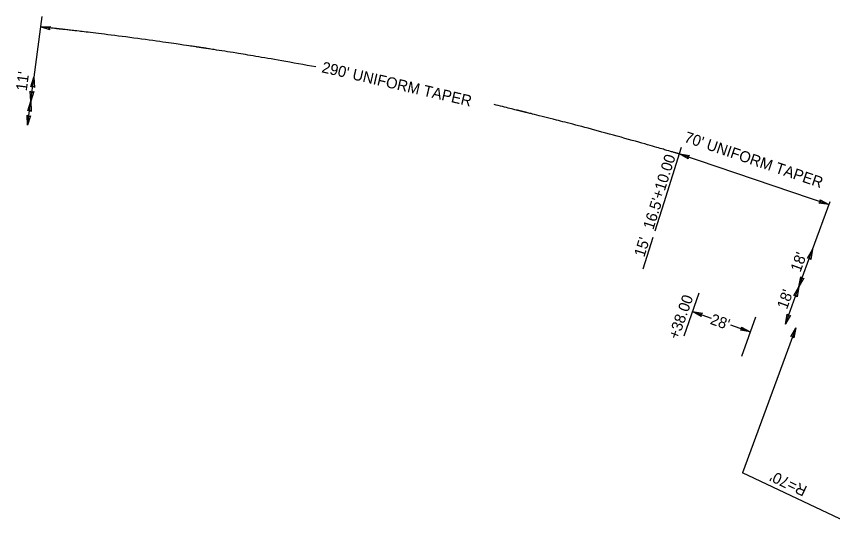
# Model space of a CAD drawing. Extents: x 2320991 to 2332664, y 598057 to 612602.
# Drawn here: x 2328502.8 to 2328873.9, y 607955.8 to 608193.1 of the extents above; entities that cross this region are included whole.
import ezdxf

# ---------------------------------------------------------------- set-up
doc = ezdxf.new("R2010")
doc.units = 0
for name, color, linetype in [('Prop Dimension', 7, 'Continuous'), ('Prop Dimension Text', 7, 'Continuous'), ('Prop Terminator CELL', 7, 'Continuous')]:
    doc.layers.add(name, color=color, linetype=linetype)

msp = doc.modelspace()

# ---------------------------------------------------------------- linework, layer by layer
at = {"layer": 'Prop Dimension'}
for p, q in [((2328514.32, 608193.06), (2328510.73, 608165.39)), ((2328509.32, 608154.49), (2328510.73, 608165.39)), ((2328507.91, 608143.58), (2328509.32, 608154.49)), ((2328797.22, 608108.44), (2328805.16, 608133.59)), ((2328804.19, 608130.53), (2328872.17, 608107.52)), ((2328793.16, 608095.56), (2328797.22, 608108.44)), ((2328864.7, 608087.11), (2328872.67, 608109)), ((2328787.75, 608078.4), (2328792.26, 608092.7)), ((2328858.54, 608070.19), (2328864.7, 608087.11)), ((2328852.37, 608053.28), (2328858.54, 608070.19)), ((2328813.01, 608067.26), (2328806.15, 608047.83)), ((2328810.09, 608058.98), (2328818.6, 608055.98)), ((2328838.81, 608056.43), (2328832.48, 608038.53)), ((2328827.41, 608052.87), (2328836.42, 608049.68)), ((2328857.08, 608051.56), (2328832.86, 607985.72)), ((2328896.13, 607955.8), (2328832.86, 607985.72))]:
    msp.add_line(p, q, dxfattribs=at)
for points in [[(2328586.95, 608178.82), (2328586.94, 608178.82), (2328586.93, 608178.82)], [(2328732.6, 608149.89), (2328732.59, 608149.89), (2328732.59, 608149.89)]]:
    msp.add_lwpolyline(points, dxfattribs=at)
for points in [[(2328586.93, 608178.82), (2328586.74, 608178.85), (2328586.46, 608178.89), (2328586.17, 608178.94), (2328585.98, 608178.97), (2328585.88, 608178.98), (2328585.6, 608179.02), (2328585.41, 608179.05), (2328585.17, 608179.09), (2328585.1, 608179.1), (2328585.02, 608179.11), (2328584.99, 608179.12), (2328584.96, 608179.12), (2328584.95, 608179.12), (2328584.84, 608179.14), (2328583.99, 608179.27), (2328581.61, 608179.62), (2328576.27, 608180.41), (2328565.6, 608181.94), (2328550.33, 608184), (2328538.1, 608185.5), (2328530.45, 608186.4), (2328528.15, 608186.67), (2328525.47, 608186.97), (2328524.23, 608187.11), (2328523.7, 608187.17), (2328523.55, 608187.19), (2328523.5, 608187.19), (2328523.49, 608187.19), (2328523.48, 608187.19), (2328523.46, 608187.2), (2328523.43, 608187.2), (2328523.2, 608187.23), (2328522.99, 608187.25), (2328522.42, 608187.31), (2328522.03, 608187.36), (2328521.62, 608187.4), (2328521.58, 608187.41), (2328521.54, 608187.41), (2328521.52, 608187.41), (2328521.51, 608187.41), (2328521.5, 608187.41), (2328521.45, 608187.42), (2328521.31, 608187.44), (2328521.16, 608187.45), (2328520.88, 608187.48), (2328520.69, 608187.5), (2328519.74, 608187.61), (2328517.48, 608187.86), (2328515.21, 608188.11), (2328513.7, 608188.28)], [(2328638.94, 608170.06), (2328633.79, 608171.01), (2328622.56, 608173.03), (2328611.32, 608174.94), (2328602.18, 608176.43), (2328597.61, 608177.17), (2328592.27, 608178), (2328589.89, 608178.37), (2328589.03, 608178.5), (2328588.93, 608178.52), (2328588.91, 608178.52), (2328588.89, 608178.52), (2328588.85, 608178.53), (2328588.77, 608178.54), (2328588.7, 608178.55), (2328588.46, 608178.59), (2328588.27, 608178.62), (2328587.98, 608178.66), (2328587.89, 608178.68), (2328587.7, 608178.7), (2328587.42, 608178.75), (2328587.14, 608178.79), (2328586.95, 608178.82)], [(2328732.59, 608149.89), (2328732.4, 608149.94), (2328732.12, 608150.01), (2328731.83, 608150.08), (2328731.65, 608150.12), (2328731.55, 608150.15), (2328731.27, 608150.21), (2328731.09, 608150.26), (2328730.85, 608150.32), (2328730.78, 608150.33), (2328730.7, 608150.35), (2328730.67, 608150.36), (2328730.65, 608150.37), (2328730.65, 608150.37), (2328730.63, 608150.37), (2328730.53, 608150.39), (2328729.68, 608150.6), (2328727.34, 608151.17), (2328723.88, 608152.01), (2328721.16, 608152.66), (2328719.95, 608152.95)], [(2328804.19, 608130.53), (2328804, 608130.58), (2328803.72, 608130.66), (2328803.45, 608130.75), (2328803.26, 608130.8), (2328803.17, 608130.83), (2328802.89, 608130.91), (2328802.71, 608130.96), (2328802.48, 608131.03), (2328802.41, 608131.05), (2328802.33, 608131.07), (2328802.29, 608131.08), (2328802.28, 608131.09), (2328802.27, 608131.09), (2328802.26, 608131.09), (2328802.16, 608131.12), (2328801.32, 608131.37), (2328799, 608132.05), (2328793.81, 608133.56), (2328783.41, 608136.53), (2328768.51, 608140.65), (2328756.56, 608143.81), (2328747.58, 608146.13), (2328743.09, 608147.27), (2328737.84, 608148.59), (2328735.5, 608149.17), (2328734.65, 608149.38), (2328734.55, 608149.41), (2328734.54, 608149.41), (2328734.51, 608149.42), (2328734.48, 608149.42), (2328734.39, 608149.44), (2328734.32, 608149.46), (2328734.09, 608149.52), (2328733.9, 608149.57), (2328733.62, 608149.64), (2328733.53, 608149.66), (2328733.34, 608149.7), (2328733.06, 608149.77), (2328732.79, 608149.84), (2328732.6, 608149.89)]]:
    msp.add_open_spline(points, degree=3, dxfattribs=at)
at = {"layer": 'Prop Terminator CELL'}
for points in [[(2328518.05, 608186.89), (2328513.7, 608188.28), (2328518.29, 608188.44), (2328517.61, 608187.73)], [(2328509.39, 608161.03), (2328510.73, 608165.39), (2328510.95, 608160.8), (2328510.23, 608161.48)], [(2328510.67, 608158.85), (2328509.32, 608154.49), (2328509.11, 608159.08), (2328509.83, 608158.4)], [(2328507.97, 608150.12), (2328509.32, 608154.49), (2328509.53, 608149.89), (2328508.81, 608150.57)], [(2328509.26, 608147.94), (2328507.91, 608143.58), (2328507.7, 608148.17), (2328508.42, 608147.49)], [(2328808.2, 608128.35), (2328804.19, 608130.53), (2328808.73, 608129.83), (2328807.93, 608129.26)], [(2328868.16, 608109.7), (2328872.17, 608107.52), (2328867.63, 608108.22), (2328868.43, 608108.79)], [(2328862.43, 608083.14), (2328864.7, 608087.11), (2328863.9, 608082.58), (2328863.34, 608083.39)], [(2328860.8, 608074.16), (2328858.54, 608070.19), (2328859.33, 608074.72), (2328859.89, 608073.9)], [(2328856.27, 608066.23), (2328858.54, 608070.19), (2328857.74, 608065.67), (2328857.18, 608066.48)], [(2328814.08, 608056.76), (2328810.09, 608058.98), (2328814.62, 608058.23), (2328813.81, 608057.67)], [(2328854.64, 608057.24), (2328852.37, 608053.28), (2328853.17, 608057.81), (2328853.73, 608056.99)], [(2328832.44, 608051.91), (2328836.42, 608049.68), (2328831.89, 608050.44), (2328832.7, 608051)], [(2328854.8, 608047.6), (2328857.08, 608051.56), (2328856.27, 608047.04), (2328855.72, 608047.85)], [(2328854.8, 608047.6), (2328857.08, 608051.56), (2328856.27, 608047.04), (2328855.72, 608047.85)]]:
    msp.add_lwpolyline(points, close=True, dxfattribs=at)

# ---------------------------------------------------------------- texts
at = {"layer": 'Prop Dimension Text'}
for s, rotation, p in [("290' UNIFORM TAPER", 347.0309, (2328641.27, 608167.69)), ("11'", 82.6213, (2328507.5, 608158.97)), ("70' UNIFORM TAPER", 341.3041, (2328806.01, 608136.14)), ('+10.00', 72.4932, (2328796.33, 608109.72)), ("16.5'", 72.4932, (2328792.31, 608095.86)), ("15'", 72.4932, (2328788.2, 608083.39)), ("18'", 69.9865, (2328859.2, 608076.53)), ('+38.00', 70.3319, (2328803.65, 608046)), ("18'", 69.9865, (2328853.04, 608059.62)), ("28'", 340.5425, (2328817.79, 608053.44)), ("R=70'", 154.6929, (2328862.68, 607979.33))]:
    msp.add_text(s, height=5, rotation=rotation, dxfattribs=at).set_placement(p)

doc.saveas('drawing.dxf')
